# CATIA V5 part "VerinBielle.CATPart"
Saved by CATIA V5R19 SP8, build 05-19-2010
Part number: VérinBielle
Bounding box of the stored display mesh (mm): x -90 to 110, y -40 to 40, z -40 to 40
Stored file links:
  J:\Travail\2e année\IAO\Projet\VerinBielle.CATPart
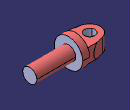
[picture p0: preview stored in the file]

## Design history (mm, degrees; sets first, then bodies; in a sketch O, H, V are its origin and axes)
Body1 (main body)
  Sketch1 on yz-plane, origin (0, 0, 0), H (0, 1, 0), V (0, 0, 1)
    circle A1 centre (0, 0) radius 20
    radius A1 = 20
  Pad1: profile Sketch1, direction (1, 0, 0), length 110
  Sketch2 on start face of Pad1, origin (0, 0, 0), H (0, -1, 0), V (0, 0, 1)
    circle A1 centre (0, 0) radius 40
    radius A1 = 40
  Pad2: profile Sketch2, direction (-1, 0, 0), length 20
  SolidCombine1: FirstComponentProfile Sketch4, FirstComponentDirection Sketch4, SecondComponentProfile Sketch5, SecondComponentDirection Sketch5
  Sketch3 on face of SolidCombine1 from Sketch4.L2, origin (-63.3728, 12.2345, -20), H (1, 0, 0), V (0, -1, 0)
    point P1 (3.3728, 12.2345)
    reference projected arc E1 centre (3.3728, 12.2345) radius 30 from (2.4568, 42.2205) to (2.4568, -17.7515) ccw from edge [face of SolidCombine1 from Sketch4.L2 | face of SolidCombine1 from Sketch5.A1]
    concentricity: P1 E1
  Hole1: placed by Sketch3, at (-60, 0, -20) direction (0, 0, 1), diameter 30, through (limit type 6)
  Sketch4 on end face of Pad2, origin (-20, 0, 0), H (0, -1, 0), V (0, 0, 1)
    arc A1 centre (0, 0) radius 40 from (34.641, -20) to (34.641, 20) ccw
    point P1 (0, 0)
    reference projected circle E1 centre (0, 0) radius 40 from edge [face of Pad2 from Sketch2.A1 | end face of Pad2]
    line L1 (-34.641, 20) -> (34.641, 20)
    point P2 (-34.641, 20)
    line L2 (34.641, -20) -> (-34.641, -20)
    arc A2 centre (0, 0) radius 40 from (-34.641, 20) to (-34.641, -20) ccw
    reference projected line E2 (29.986, 0) -> (44.2515, 0) from Sketch5.A3
    reference projected line E3 (-29.986, 0) -> (29.986, 0) from Sketch5.A1
    reference projected line E4 (-29.986, 0) -> (29.986, 0) from Sketch5.A1
    distance L1 E2 = 20
    distance E3 E4 = 0 (reference)
    distance L2 H = 20
    coincidence: P1 H, A1 E1, P2 A1, A1 A2
    horizontal: L1 H, L2 H
  Sketch5 on xy-plane, origin (0, 0, 0), H (1, 0, 0), V (0, 1, 0)
    arc A1 centre (-60, 0) radius 30 from (-65.9825, 29.3974) to (-65.9825, -29.3974) ccw
    point P1 (-60, 0)
    line L1 (-31.4513, 40.1315) -> (-20, 45)
    point P2 (-55.933, 29.723)
    point P3 (-20, 45)
    axis line L2 (-132.7013, 0) -> (62.1574, 0)
    point P4 (-132.7013, 0)
    reference projected line E1 (-20, -45) -> (-20, 45) from edge [face of Pad2 from Sketch2.A1 | end face of Pad2]
    point P6 (-20, -45)
    line L3 (-31.4513, -40.1315) -> (-20, -45)
    arc A2 centre (-101.8777, 205.7821) radius 180 from (-65.9825, 29.3974) to (-31.4513, 40.1315) ccw
    point P7 (-65.9825, 29.3974)
    point P8 (-31.4513, 40.1315)
    point P10 (-31.4513, -40.1315)
    point P11 (-65.9825, -29.3974)
    arc A3 centre (-101.8777, -205.7821) radius 180 from (-65.9825, -29.3974) to (-31.4513, -40.1315) cw
    line L4 (-20, 45) -> (-20, -45)
    radius A1 = 30
    distance P3 L2 = 45
    radius A2 = 180
    distance P1 L4 = 40
    coincidence: P1 H, P2 A1, P4 H, P3 E1, L1 P2
    horizontal: L2 H
    symmetry: P3 P6 L2, L1 L3 L2, P8 P10 L2, P7 P11 L2, A2 A3 L2
    tangency: A2 A1, A2 L1
    vertical: L4 V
